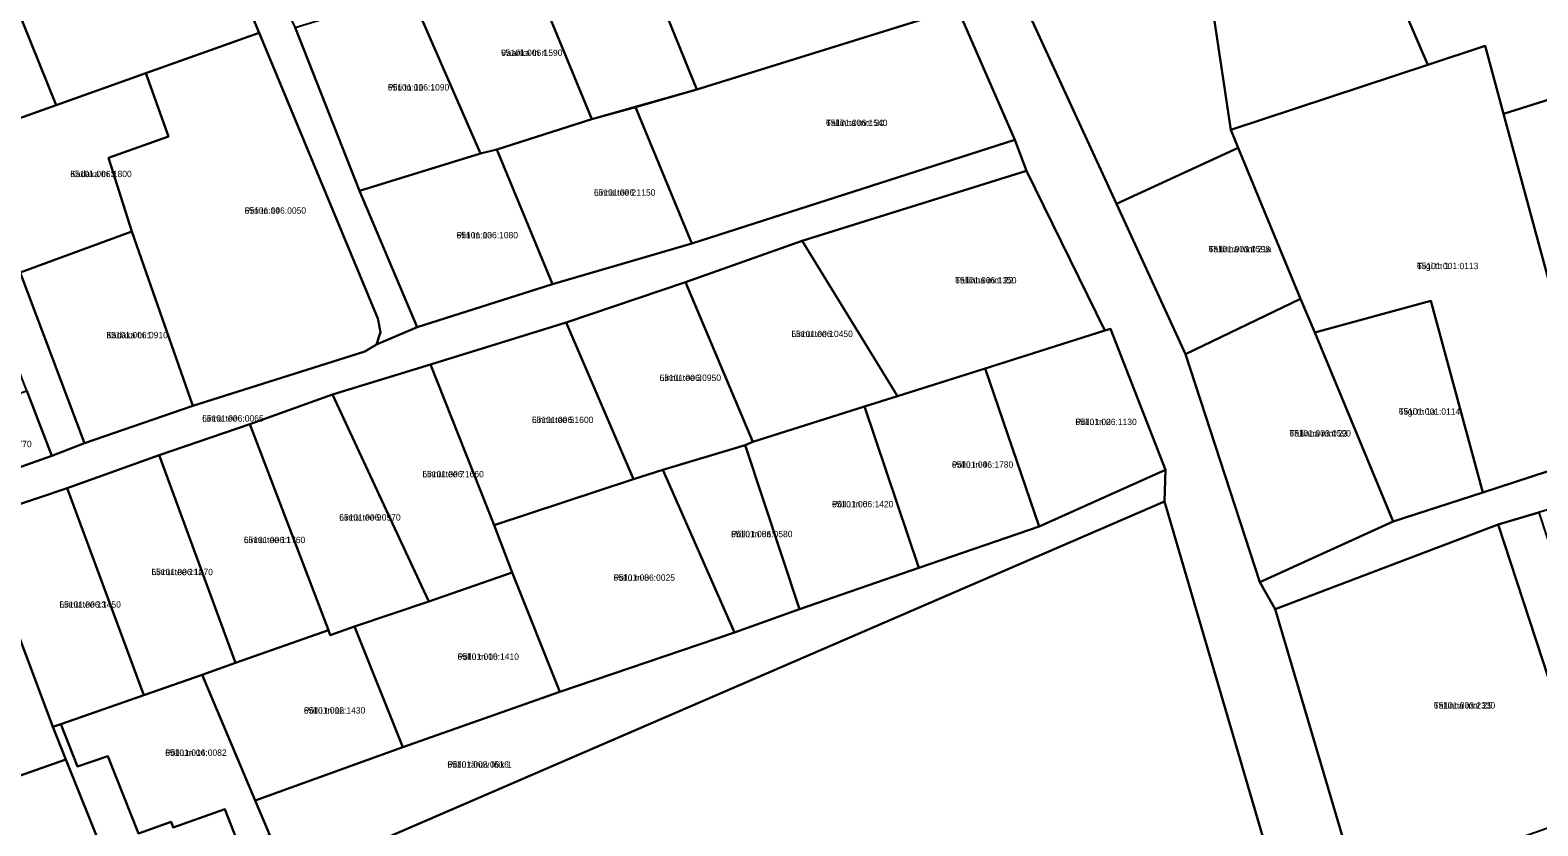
# Model space of a CAD drawing. Extents: x 556044 to 574504, y 6567077 to 6586269.
# Drawn here: x 561223.9 to 561579.8, y 6581344.1 to 6581531.9 of the extents above; entities that cross this region are included whole.
import ezdxf

# ---------------------------------------------------------------- set-up
doc = ezdxf.new("R2010")
doc.units = 0
for name, color, linetype in [('L_AADRESS', 7, 'Continuous'), ('PIIR', 7, 'Continuous'), ('TUNNUS', 7, 'Continuous')]:
    doc.layers.add(name, color=color, linetype=linetype)

msp = doc.modelspace()

# ---------------------------------------------------------------- linework, layer by layer
at = {"layer": 'PIIR'}
for points in [[(561524.93, 6581307.49), (561491.73, 6581420.63), (561491.94, 6581428.14), (561478.96, 6581461.41), (561477.62, 6581460.99), (561459.15, 6581498.72), (561456.34, 6581506.01), (561442.81, 6581537.04), (561435.94, 6581553.48), (561426.52, 6581574.92), (561422.46, 6581582.74), (561407.77, 6581613.72), (561391.94, 6581647.98), (561388.51, 6581655.94), (561372.63, 6581689.33), (561369.06, 6581688.16), (561348.85, 6581730.06), (561348.03, 6581740.19), (561334.55, 6581772.4)], [(561366.17, 6581745.64), (561371.19, 6581732.22), (561399.08, 6581734.47), (561420.56, 6581685.9), (561391.38, 6581680.8), (561403.41, 6581655.08), (561438.73, 6581579.49), (561444.23, 6581569.32), (561480.35, 6581490.91), (561496.69, 6581455.44), (561514.23, 6581401.65), (561517.83, 6581395.22), (561537.73, 6581327.99)], [(561197.21, 6581420.19), (561229.03, 6581431.45), (561236.77, 6581434.42), (561262.3, 6581443.26), (561302.89, 6581456.04), (561305.66, 6581457.75), (561315.26, 6581461.77), (561347.18, 6581471.96), (561380.12, 6581481.52), (561456.34, 6581506.01), (561459.15, 6581498.72), (561406.16, 6581482.2), (561378.6, 6581472.39), (561350.47, 6581462.89), (561318.4, 6581453.01), (561295.29, 6581445.88), (561275.73, 6581438.89), (561254.39, 6581431.62), (561232.68, 6581423.83), (561210.87, 6581416.48)]]:
    msp.add_lwpolyline(points, dxfattribs=at)
for points in [[(561223.92, 6581655.37), (561234.85, 6581660.17), (561240.21, 6581646.64), (561253.85, 6581612.07), (561256.23, 6581604.63), (561270.59, 6581570.5), (561283.11, 6581539.32), (561286.45, 6581532.52), (561301.68, 6581494), (561315.26, 6581461.77), (561305.66, 6581457.75), (561306.65, 6581460.65), (561305.98, 6581463.86), (561277.97, 6581531.26), (561241.95, 6581617.15), (561237.31, 6581628.21), (561234.5, 6581634.79)], [(561157.99, 6581612.48), (561165.4, 6581618.41), (561171.98, 6581597.55), (561175.27, 6581589.41), (561208.79, 6581506.62), (561212.14, 6581507.81), (561210.22, 6581503.5), (561221.52, 6581474.69), (561236.77, 6581434.42), (561229.03, 6581431.45), (561223.14, 6581446.77), (561218.48, 6581458.7), (561208.99, 6581483.75), (561204.95, 6581491.41), (561194.77, 6581520.27), (561184.86, 6581547.04), (561174.45, 6581573.3)], [(561241.95, 6581617.15), (561277.97, 6581531.26), (561251.22, 6581521.73), (561230.01, 6581514.18), (561220.08, 6581539.06), (561215.46, 6581537.15), (561205.42, 6581562.26), (561225.85, 6581570.44), (561212.25, 6581604.8)], [(561175.27, 6581589.41), (561212.25, 6581604.8), (561225.85, 6581570.44), (561205.42, 6581562.26), (561215.46, 6581537.15), (561220.08, 6581539.06), (561230.01, 6581514.18), (561212.14, 6581507.81), (561208.79, 6581506.62)], [(561524.15, 6581591.15), (561546.5, 6581540.96), (561553.88, 6581523.71), (561507.33, 6581508.4), (561500.3, 6581555.59), (561487.74, 6581582.83)], [(561546.5, 6581540.96), (561579.61, 6581554.85), (561621.06, 6581572.61), (561655.95, 6581587.05), (561658.6, 6581588.19), (561673.96, 6581525.06), (561684.95, 6581483.18), (561687, 6581458.12), (561679.96, 6581455.87), (561672.27, 6581484.87), (561614.24, 6581469.57), (561600.53, 6581521.19), (561571.7, 6581512.12), (561567.42, 6581528.16), (561553.88, 6581523.71)], [(561444.23, 6581569.32), (561487.74, 6581582.83), (561500.3, 6581555.59), (561507.33, 6581508.4), (561509.1, 6581504.15), (561480.35, 6581490.91)], [(561365.73, 6581556.07), (561374.28, 6581535.11), (561381.3, 6581517.9), (561356.53, 6581510.88), (561340.69, 6581549.29)], [(561435.94, 6581553.48), (561442.81, 6581537.04), (561381.3, 6581517.9), (561374.28, 6581535.11)], [(561340.69, 6581549.29), (561356.53, 6581510.88), (561334.07, 6581503.76), (561330.23, 6581502.77), (561313.6, 6581540.86)], [(561313.6, 6581540.86), (561330.23, 6581502.77), (561301.68, 6581494), (561286.45, 6581532.52)], [(561366.8, 6581513.71), (561381.3, 6581517.9), (561442.81, 6581537.04), (561456.34, 6581506.01), (561380.12, 6581481.52)], [(561306.65, 6581460.65), (561305.66, 6581457.75), (561302.89, 6581456.04), (561262.3, 6581443.26), (561247.93, 6581484.38), (561242.42, 6581501.77), (561256.55, 6581506.8), (561251.22, 6581521.73), (561277.97, 6581531.26), (561305.98, 6581463.86)], [(561509.1, 6581504.15), (561507.33, 6581508.4), (561553.88, 6581523.71), (561567.42, 6581528.16), (561571.7, 6581512.12), (561593.6, 6581431.51), (561566.84, 6581422.82), (561554.58, 6581467.98), (561527.15, 6581460.51), (561523.83, 6581468.46)], [(561210.22, 6581503.5), (561212.14, 6581507.81), (561251.22, 6581521.73), (561256.55, 6581506.8), (561242.42, 6581501.77), (561247.93, 6581484.38), (561221.52, 6581474.69)], [(561571.7, 6581512.12), (561600.53, 6581521.19), (561614.24, 6581469.57), (561621.96, 6581440.5), (561593.6, 6581431.51)], [(561334.07, 6581503.76), (561356.53, 6581510.88), (561366.8, 6581513.71), (561380.12, 6581481.52), (561347.18, 6581471.96)], [(561301.68, 6581494), (561330.23, 6581502.77), (561334.07, 6581503.76), (561347.18, 6581471.96), (561315.26, 6581461.77)], [(561480.35, 6581490.91), (561509.1, 6581504.15), (561523.83, 6581468.46), (561496.69, 6581455.44)], [(561406.16, 6581482.2), (561459.15, 6581498.72), (561477.62, 6581460.99), (561450.39, 6581452.39), (561428.65, 6581445.52)], [(561221.52, 6581474.69), (561247.93, 6581484.38), (561262.3, 6581443.26), (561236.77, 6581434.42)], [(561406.16, 6581482.2), (561428.65, 6581445.52), (561420.89, 6581443.07), (561394.53, 6581434.76), (561378.6, 6581472.39)], [(561378.6, 6581472.39), (561394.53, 6581434.76), (561392.68, 6581433.98), (561373.23, 6581428.14), (561366.34, 6581425.92), (561350.47, 6581462.89)], [(561496.69, 6581455.44), (561523.83, 6581468.46), (561527.15, 6581460.51), (561545.69, 6581415.95), (561514.23, 6581401.65)], [(561545.69, 6581415.95), (561527.15, 6581460.51), (561554.58, 6581467.98), (561566.84, 6581422.82)], [(561350.47, 6581462.89), (561366.34, 6581425.92), (561333.47, 6581415.08), (561318.4, 6581453.01)], [(561491.94, 6581428.14), (561462.09, 6581414.77), (561449.36, 6581452.06), (561477.62, 6581460.99), (561478.96, 6581461.41)], [(561514.23, 6581401.65), (561545.69, 6581415.95), (561566.84, 6581422.82), (561593.6, 6581431.51), (561621.96, 6581440.5), (561679.96, 6581455.87), (561687, 6581458.12), (561687.32, 6581448.38), (561685.46, 6581448.07), (561675.84, 6581446.48), (561632.12, 6581433.44), (561624.42, 6581431.25), (561570.46, 6581415.2), (561517.83, 6581395.22)], [(561318.4, 6581453.01), (561333.47, 6581415.08), (561337.7, 6581403.93), (561318.01, 6581397.07), (561316.31, 6581400.76), (561295.29, 6581445.88)], [(561433.73, 6581404.99), (561420.89, 6581443.07), (561428.65, 6581445.52), (561449.36, 6581452.06), (561462.09, 6581414.77)], [(561229.03, 6581431.45), (561197.21, 6581420.19), (561190.24, 6581435.74), (561223.14, 6581446.77)], [(561316.31, 6581400.76), (561318.01, 6581397.07), (561300.47, 6581391.16), (561294.76, 6581389.1), (561294.33, 6581390.3), (561275.73, 6581438.89), (561295.29, 6581445.88)], [(561433.73, 6581404.99), (561405.51, 6581395.29), (561392.68, 6581433.98), (561394.53, 6581434.76), (561420.89, 6581443.07)], [(561275.73, 6581438.89), (561294.33, 6581390.3), (561272.41, 6581382.56), (561254.39, 6581431.62)], [(561250.78, 6581374.98), (561232.68, 6581423.83), (561254.39, 6581431.62), (561272.41, 6581382.56), (561264.48, 6581379.78)], [(561390.15, 6581389.72), (561373.23, 6581428.14), (561392.68, 6581433.98), (561405.51, 6581395.29)], [(561156.54, 6581287.57), (561142.08, 6581290.69), (561143.25, 6581300.49), (561148.41, 6581299.73), (561162.27, 6581310.63), (561194.83, 6581321.35), (561241.19, 6581337.71), (561241.29, 6581337.45), (561244.33, 6581329.07), (561273.25, 6581339.37), (561280.48, 6581341.95), (561277.04, 6581350.09), (561311.86, 6581362.68), (561348.98, 6581375.76), (561390.15, 6581389.72), (561405.51, 6581395.29), (561433.73, 6581404.99), (561462.09, 6581414.77), (561491.94, 6581428.14), (561491.73, 6581420.63), (561289.22, 6581333.22), (561277.91, 6581329.15)], [(561366.34, 6581425.92), (561373.23, 6581428.14), (561390.15, 6581389.72), (561348.98, 6581375.76), (561337.7, 6581403.93), (561333.47, 6581415.08)], [(561232.68, 6581423.83), (561250.78, 6581374.98), (561231.11, 6581368.11), (561229.26, 6581367.46), (561210.87, 6581416.48)], [(561491.73, 6581420.63), (561524.93, 6581307.49), (561488.6, 6581295.9), (561494.88, 6581264.01), (561466.05, 6581266.08), (561463.98, 6581234.8), (561443.47, 6581236.27), (561402.92, 6581239.17), (561289.06, 6581247.28), (561285.38, 6581257.48), (561289.22, 6581333.22)], [(561210.87, 6581416.48), (561229.26, 6581367.46), (561232.35, 6581359.79), (561204.33, 6581349.93), (561202.03, 6581356.84), (561185.2, 6581407.17)], [(561570.46, 6581415.2), (561580.05, 6581418.04), (561591.36, 6581383.64), (561602.83, 6581345.63), (561592.72, 6581347.29)], [(561517.83, 6581395.22), (561570.46, 6581415.2), (561592.72, 6581347.29), (561537.73, 6581327.99)], [(561311.86, 6581362.68), (561300.47, 6581391.16), (561318.01, 6581397.07), (561337.7, 6581403.93), (561348.98, 6581375.76)], [(561277.04, 6581350.09), (561264.48, 6581379.78), (561272.41, 6581382.56), (561294.33, 6581390.3), (561294.76, 6581389.1), (561300.47, 6581391.16), (561311.86, 6581362.68)], [(561231.11, 6581368.11), (561250.95, 6581375.05), (561264.48, 6581379.78), (561277.05, 6581350.07), (561280.48, 6581341.95), (561273.25, 6581339.37), (561269.83, 6581348.07), (561257.68, 6581343.73), (561257.17, 6581345.03), (561249.48, 6581342.28), (561242.28, 6581360.58), (561235.05, 6581358.1)], [(561229.26, 6581367.46), (561231.11, 6581368.11), (561235.05, 6581358.1), (561242.28, 6581360.58), (561249.48, 6581342.28), (561257.17, 6581345.03), (561257.68, 6581343.73), (561269.83, 6581348.07), (561273.25, 6581339.37), (561244.33, 6581329.07), (561241.29, 6581337.45), (561241.19, 6581337.71), (561232.35, 6581359.79)], [(561186.63, 6581343.99), (561204.33, 6581349.93), (561232.35, 6581359.79), (561241.19, 6581337.71), (561194.83, 6581321.35)]]:
    msp.add_lwpolyline(points, close=True, dxfattribs=at)

# ---------------------------------------------------------------- texts
at = {"layer": 'L_AADRESS'}
for s, p in [('Vaarika tn 4', (561335.07, 6581525.81)), ('Piiri tn 11', (561308.34, 6581517.65)), ('Tallinna mnt 20', (561411.77, 6581509.28)), ('Kadaka tn 3', (561233.38, 6581497.21)), ('Linnu tee 2', (561357.01, 6581492.84)), ('Piiri tn 14', (561274.54, 6581488.57)), ('Piiri tn 13', (561324.57, 6581482.77)), ('Tallinna mnt 21a', (561502.09, 6581479.48)), ('Tiigi tn 1', (561551.29, 6581475.49)), ('Tallinna mnt 22', (561442.26, 6581472.12)), ('Kadaka tn 1', (561241.91, 6581459.19)), ('Linnu tee 1', (561403.62, 6581459.46)), ('Linnu tee 3', (561372.5, 6581449.12)), ('Tiigi tn 1a', (561547, 6581441.14)), ('Linnu tee', (561264.52, 6581439.53)), ('Linnu tee 5', (561342.37, 6581439.2)), ('Põllu tn 2', (561470.65, 6581438.7)), ('Tallinna mnt 23', (561521.19, 6581436)), ('Linnu tee 7', (561316.5, 6581426.39)), ('Põllu tn 4', (561441.49, 6581428.62)), ('Põllu tn 6', (561413.2, 6581419.29)), ('Linnu tee 9', (561296.87, 6581416.17)), ('Põllu tn 8a', (561389.37, 6581412.24)), ('Linnu tee 11', (561274.36, 6581410.84)), ('Linnu tee 11a', (561252.54, 6581403.28)), ('Põllu tn 8', (561361.63, 6581401.95)), ('Linnu tee 13', (561230.82, 6581395.61)), ('Põllu tn 10', (561324.79, 6581383.3)), ('Põllu tn 12', (561288.52, 6581370.62)), ('Tallinna mnt 25', (561555.27, 6581371.79)), ('Põllu tn 14', (561255.79, 6581360.64)), ('Põllu tänav lõik 1', (561322.4, 6581357.86))]:
    msp.add_text(s, height=1.5, dxfattribs=at).set_placement(p)
at = {"layer": 'TUNNUS'}
for s, p in [('65101:006:1590', (561335.07, 6581525.81)), ('65101:006:1090', (561308.34, 6581517.65)), ('65101:006:1540', (561411.77, 6581509.28)), ('65101:006:1800', (561233.38, 6581497.21)), ('65101:006:1150', (561357.01, 6581492.84)), ('65101:006:0050', (561274.54, 6581488.57)), ('65101:006:1080', (561324.57, 6581482.77)), ('65101:003:0598', (561502.09, 6581479.48)), ('65101:001:0113', (561551.29, 6581475.49)), ('65101:006:1350', (561442.26, 6581472.12)), ('65101:006:0910', (561241.91, 6581459.19)), ('65101:006:0450', (561403.62, 6581459.46)), ('65101:006:0950', (561372.5, 6581449.12)), ('65101:001:0114', (561547, 6581441.14)), ('65101:006:0065', (561264.52, 6581439.53)), ('65101:006:1600', (561342.37, 6581439.2)), ('65101:006:1130', (561470.65, 6581438.7)), ('65101:006:1770', (561209.75, 6581433.48)), ('65101:003:0590', (561521.19, 6581436)), ('65101:006:1660', (561316.5, 6581426.39)), ('65101:006:1780', (561441.49, 6581428.62)), ('65101:006:1420', (561413.2, 6581419.29)), ('65101:006:0970', (561296.87, 6581416.17)), ('65101:006:0580', (561389.37, 6581412.24)), ('65101:006:1760', (561274.36, 6581410.84)), ('65101:006:1270', (561252.54, 6581403.28)), ('65101:006:0025', (561361.63, 6581401.95)), ('65101:006:1450', (561230.82, 6581395.61)), ('65101:006:1410', (561324.79, 6581383.3)), ('65101:006:1430', (561288.52, 6581370.62)), ('65101:003:2330', (561555.27, 6581371.79)), ('65101:006:0082', (561255.79, 6581360.64)), ('65101:003:0616', (561322.4, 6581357.86))]:
    msp.add_text(s, height=1.5, dxfattribs=at).set_placement(p)

doc.saveas('drawing.dxf')
